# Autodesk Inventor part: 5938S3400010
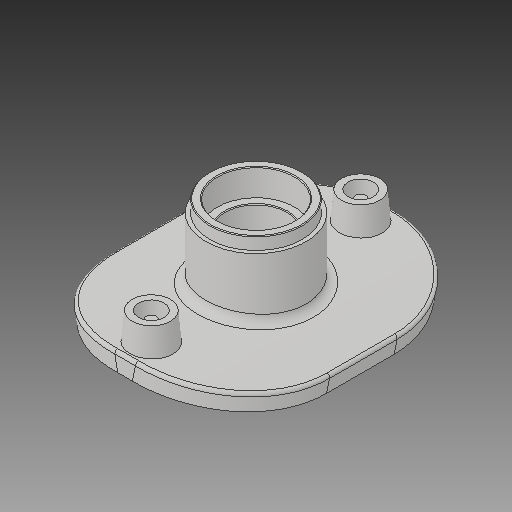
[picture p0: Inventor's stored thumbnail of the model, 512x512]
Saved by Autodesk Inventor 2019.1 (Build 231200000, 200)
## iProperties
Created: 2017-08
Part Number: 5938S3400010
Material: Generic
Description: PLASSON SENSOR ADAPTOR WITH STAINLESS STEEL THREAD 4''16''IPSx1''
Document SubType Name: Modeling
Designer: Кирилл
Density: 1 g/cm^3
Appearance: Default
Author: Кирилл
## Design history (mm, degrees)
derived "5938S.ipt"
feature "Solid1::5938S.ipt"
feature "Solid2::5938S.ipt"
feature "Solid3::5938S.ipt"
tag "TaggingFeature1"
body "Solid1"
other parameters: "d0" = 404.6, "d1" = 84.836, "d3" = 102.87, "d4" = 0, "d5" = 38.1762, "d11" = 262.99, "d38" = 1.2138, "d40" = 219.826, "d41" = 15, "d42" = 41.148, "d46" = 5 deg, "d47" = 4, "d51" = 14, "d52" = 0, "d53" = 3, "d54" = 0, "d75" = 0, "d77" = 0, "d78" = 0.30291, "d82" = 35.052, "d83" = 39.3783, "d84" = 36.3492, "d85" = 24.2328, "d86" = 30.291, "d89" = 10.5156, "d90" = 4.90728, "d95" = 3.175, "d97" = 360 deg, "d99" = 7.0104, "d_" = 404.6, "B_" = 84.836, "H_" = 35.052, "L_" = 102.87, "G_" = 30.291
